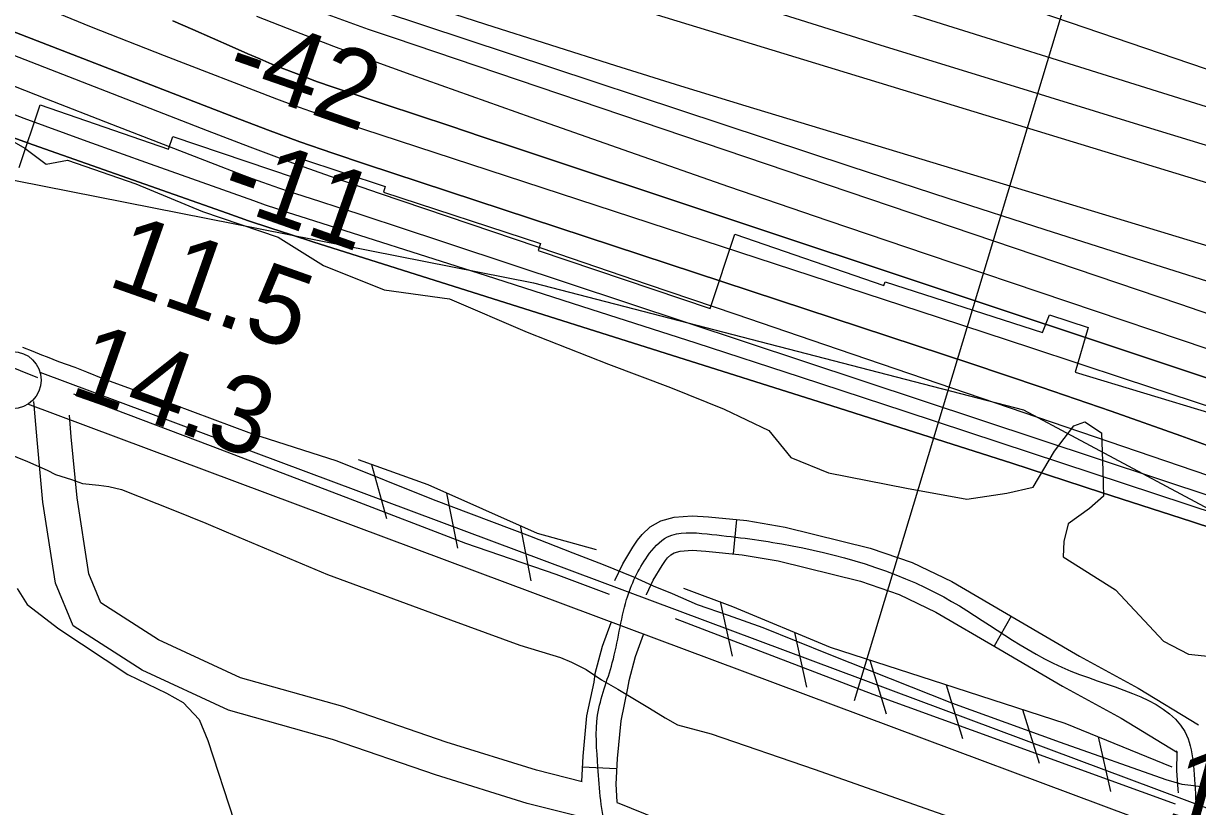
# Model space of a CAD drawing. Extents: x 3715084 to 3753216, y 488173 to 513963.
# Drawn here: x 3725388 to 3726412, y 498565 to 499247 of the extents above; entities that cross this region are included whole.
import ezdxf

# ---------------------------------------------------------------- set-up
doc = ezdxf.new("R2010")
doc.units = 0
for name, color, linetype in [('V-FLOD-BASE', 7, 'Continuous'), ('V-LEVE-TOET', 7, 'Continuous'), ('V-RIVR-EDGE', 7, 'Continuous'), ('V-RIVR-RANG', 7, 'Continuous'), ('V-ROAD-CNTR', 7, 'Continuous'), ('V-RRAP-FSHR', 7, 'Continuous'), ('V-RRAP-RVMT', 7, 'Continuous'), ('V-SITE-VEGE', 7, 'Continuous'), ('V-SURV-LINE', 7, 'Continuous'), ('V-TOPO-DPTH', 7, 'Continuous'), ('V-TOPO-MAJR', 7, 'Continuous'), ('V-TOPO-MINR', 7, 'Continuous'), ('V-TOPO-WATR', 7, 'Continuous')]:
    doc.layers.add(name, color=color, linetype=linetype)

msp = doc.modelspace()

# ---------------------------------------------------------------- linework, layer by layer
at = {"layer": 'V-FLOD-BASE'}
for points in [[(3723786.8, 499534.2), (3723869.2, 499496.9), (3723912.4, 499480.6), (3724034.1, 499437.4), (3724138.2, 499397.8), (3724259, 499355.5), (3724374, 499312.6), (3724499.4, 499266.7), (3724640.2, 499217.5), (3724785.1, 499164.3), (3724882.3, 499131.4), (3725004.5, 499087.7), (3725102.7, 499049.9), (3725207.1, 499013.5), (3725326.2, 498968.4), (3725400.8, 498938.7)], [(3725432.2, 498924.4), (3725551.2, 498879.3), (3725669.4, 498834.2), (3725773.9, 498794.2), (3725852.5, 498767.3), (3725898.9, 498749.7)], [(3725956.6, 498728.6), (3726128.8, 498662.7), (3726273.8, 498610.2), (3726392.3, 498567.1)]]:
    msp.add_lwpolyline(points, dxfattribs=at)
at = {"layer": 'V-LEVE-TOET'}
for points in [[(3725387.5, 498964.9), (3725396.6, 498961.5), (3725404.3, 498958.4), (3725409.1, 498956.5), (3725419.1, 498952.6), (3725433.2, 498947.5), (3725443.4, 498943.6), (3725457.7, 498937.8), (3725501.6, 498921.7), (3725587.2, 498889.7), (3725661.5, 498865.9), (3725745.6, 498832.3), (3725829.6, 498800.5), (3725867.4, 498785.9), (3725893.7, 498775.6), (3725920.1, 498764.8), (3725937.4, 498757), (3725953.9, 498750.4)], [(3725373.5, 498873), (3725392.1, 498865.3), (3725409, 498857.9), (3725416.3, 498854), (3725430.3, 498849.7), (3725439.9, 498846.3), (3725454.3, 498844.8), (3725462.9, 498843.6), (3725473.8, 498841.1), (3725520.2, 498822.6), (3725547.5, 498811.8), (3725565.2, 498804), (3725592.8, 498792.5), (3725653.6, 498766.8), (3725760.8, 498727.4), (3725821.2, 498705.5), (3725856.7, 498694.5), (3725866.2, 498690.6), (3725879, 498684.1), (3725892.2, 498675.3), (3725900.4, 498670.5), (3725906.4, 498667), (3725921, 498658.3), (3725934.2, 498650.4), (3725947.9, 498642.1), (3725958.4, 498636)], [(3725953.9, 498750.4), (3725975.8, 498740.8), (3726002.6, 498731.4), (3726033, 498720.9), (3726090.4, 498697.5), (3726197.3, 498655.1), (3726292.1, 498620.8), (3726384.3, 498588.2), (3726398.1, 498584.4), (3726406.1, 498583.3), (3726412.7, 498582.5), (3726416.3, 498581.6)], [(3725958.4, 498636), (3725987.9, 498628), (3726077.6, 498597.4), (3726210.5, 498550.6), (3726367.3, 498491.9), (3726599, 498410), (3726765.2, 498350.1), (3726863.8, 498316.9), (3726935.1, 498291.6), (3727054.7, 498243), (3727151.8, 498206.2), (3727209, 498188.4), (3727242.1, 498172.1), (3727277, 498151.6), (3727309.7, 498134.7), (3727402.2, 498100.1), (3727510.5, 498069), (3727562.5, 498053.8), (3727581.7, 498047.1), (3727583, 498046.7)]]:
    msp.add_lwpolyline(points, dxfattribs=at)
at = {"layer": 'V-RIVR-EDGE'}
msp.add_lwpolyline([(3725335.2, 499169.6), (3725389.7, 499138.3), (3725408.3, 499124.4), (3725426.9, 499128), (3725486.3, 499107.4), (3725544.5, 499083.2), (3725610.5, 499060.9), (3725650, 499036.2), (3725702.8, 499015), (3725759.8, 499007.1), (3725827.6, 498978.1), (3725898.4, 498950.3), (3725952.3, 498929.8), (3725999.1, 498911), (3726038.1, 498892.3), (3726057.2, 498868.9), (3726090.2, 498855.6), (3726158, 498842.2), (3726210.8, 498832.5), (3726245.7, 498837.8), (3726268.5, 498843.1), (3726287.2, 498874.3), (3726304, 498896.5), (3726313.7, 498900), (3726328, 498890.4), (3726329.2, 498857.4), (3726329.7, 498835.2), (3726317.7, 498824.4), (3726299, 498811.2), (3726295.4, 498795.6), (3726294.8, 498782.4), (3726340.3, 498753.5), (3726382.2, 498709), (3726403.8, 498697.5), (3726445.8, 498693.2)], dxfattribs=at)
at = {"layer": 'V-RIVR-RANG'}
msp.add_line((3726112.9, 498657.3), (3726390.3, 499576.4), dxfattribs=at)
at = {"layer": 'V-ROAD-CNTR'}
for p, q in [((3726009.9, 498814.8), (3726007, 498785)), ((3726249.5, 498730.5), (3726234.4, 498704.6)), ((3725905.5, 498597.6), (3725875.5, 498599))]:
    msp.add_line(p, q, dxfattribs=at)
for points in [[(3725877.4, 498554.9), (3725827.5, 498567.5), (3725747.7, 498592.5), (3725657.9, 498623.1), (3725567.2, 498648.8), (3725491.8, 498683.5), (3725431.7, 498722.3), (3725416.4, 498759.3), (3725405.5, 498830), (3725400.3, 498884.2), (3725397.5, 498917.7)], [(3725875.5, 498586.4), (3725835.7, 498596.4), (3725757, 498621), (3725666.9, 498651.8), (3725577.6, 498677), (3725506.3, 498709.9), (3725455.9, 498742.4), (3725445.5, 498767.4), (3725435.3, 498833.7), (3725430.1, 498886.9), (3725428.6, 498905.8)], [(3725904, 498761.6), (3725910.9, 498776.2), (3725919.7, 498790.9), (3725923.7, 498796.9), (3725927.7, 498801.9), (3725934.7, 498808.5), (3725943.9, 498813.6), (3725955.7, 498817), (3725971.2, 498818.1), (3725985.5, 498817.2), (3726018.9, 498813.9), (3726052.5, 498808.3), (3726126.5, 498790), (3726163, 498777.4), (3726197.7, 498760.7), (3726253.7, 498728.1), (3726308.8, 498695.8), (3726360.1, 498667.8), (3726412.7, 498635.9)], [(3725931.4, 498749.2), (3725931.4, 498749.4), (3725937.4, 498762.1), (3725945.1, 498774.9), (3725948, 498779.2), (3725949.8, 498781.5), (3725952.6, 498784.1), (3725955.5, 498785.7), (3725960.9, 498787.3), (3725971.4, 498788), (3725983.1, 498787.3), (3726014.9, 498784.2), (3726046.4, 498778.9), (3726118, 498761.2), (3726151.6, 498749.6), (3726183.6, 498734.1), (3726238.6, 498702.2), (3726294.1, 498669.7), (3726345.1, 498641.8), (3726394.3, 498612), (3726394, 498612.3), (3726393.3, 498613.4), (3726393.7, 498612.1), (3726393.6, 498596.3), (3726394.6, 498579.5), (3726394.8, 498576.8)], [(3725900.4, 498724.8), (3725892.8, 498704.1), (3725886.6, 498680.3), (3725885.6, 498673.2), (3725879.3, 498643.9), (3725876, 498608.6), (3725874.9, 498586.6)], [(3725928.6, 498714.5), (3725921.5, 498695.1), (3725916.1, 498674.4), (3725915.1, 498667.9), (3725909, 498639.4), (3725905.9, 498606.5), (3725904.9, 498584.3), (3725905.8, 498569), (3725906, 498567.8)], [(3725905.9, 498568.3), (3726015.8, 498523.8), (3726141.5, 498471.6), (3726283.2, 498412), (3726374.6, 498378.4), (3726355.2, 498260.8), (3726354.6, 498255.3), (3726352.2, 498234.1), (3726347.3, 498169.4), (3726344.4, 498110.1), (3726339.4, 498008.3), (3726336.3, 497977.2), (3726330.7, 497920.6), (3726327, 497845.4), (3726326.1, 497821), (3726325.6, 497787.2), (3726325.3, 497757.8)]]:
    msp.add_lwpolyline(points, dxfattribs=at)
msp.add_spline([(3725896.8, 497907), (3725901.6, 497928.8), (3725900.7, 497963.5), (3725897.7, 498015.4), (3725890.9, 498061.9), (3725848.5, 498171.1), (3725816.4, 498253), (3725801.2, 498306.9), (3725798.9, 498337.3), (3725811.7, 498376.3), (3725846.5, 498404.9), (3725886, 498425), (3725912.4, 498438.6), (3725916.4, 498460.8), (3725913.1, 498502), (3725897.5, 498542.1), (3725889.2, 498599.1), (3725888.9, 498644.4), (3725901.7, 498689.9), (3725914.2, 498745.1), (3725932.4, 498782.9), (3725949.7, 498799.7), (3725984.3, 498802.3), (3726049.5, 498793.6), (3726190.6, 498747.4), (3726301.5, 498682.8), (3726403.5, 498623.9), (3726408.6, 498596.7), (3726410.4, 498564)], degree=3, dxfattribs=at)
at = {"layer": 'V-RRAP-FSHR'}
for p, q in [((3725691.9, 498862.7), (3725704.8, 498815.6)), ((3725757.3, 498837.8), (3725766.7, 498789.9)), ((3725821.3, 498809.5), (3725830.7, 498761.5)), ((3725995.8, 498743.3), (3726006.3, 498695.7)), ((3726060.4, 498716.5), (3726071, 498668.8)), ((3726126.1, 498692.3), (3726140.3, 498645.6)), ((3726192.6, 498670.7), (3726207, 498624)), ((3726259.3, 498649.2), (3726273.7, 498602.6)), ((3726325.1, 498625.5), (3726335.8, 498577.9))]:
    msp.add_line(p, q, dxfattribs=at)
for points in [[(3719778.9, 501659.5), (3719780.9, 501658.9), (3720162.1, 501439.6), (3720517.2, 501248), (3721025.7, 501011.2), (3721396.9, 500844.8), (3721781.4, 500671.7), (3722343.7, 500424.7), (3722591.4, 500331.7), (3722936.5, 500157.7), (3723365.3, 499935.7), (3724002.2, 499670.3), (3724701.9, 499359), (3725287.2, 499128.8), (3725832.9, 499021), (3726260.1, 498910.4), (3726533.7, 498764.1), (3726929.4, 498511.1), (3727309.4, 498360.7), (3727495.4, 498332.2), (3727633.2, 498290.4), (3727809.2, 498206.8), (3728004.4, 498122.8), (3728249.6, 498078.8)], [(3725888, 498788.4), (3725836.6, 498802.7), (3725741.1, 498845.1), (3725680.5, 498866.8)], [(3726389.8, 498599), (3726296.5, 498637.2), (3726190.8, 498671.3), (3726092, 498703.4), (3726006.9, 498738.7), (3725964.1, 498754.6)]]:
    msp.add_lwpolyline(points, dxfattribs=at)
at = {"layer": 'V-RRAP-RVMT'}
for p, q in [((3725384.7, 499121.4), (3725402.9, 499176)), ((3725402.9, 499176), (3725514.8, 499137.6)), ((3725514.8, 499137.6), (3725518.6, 499148.5)), ((3725518.6, 499148.5), (3725624.4, 499112.9)), ((3725624.4, 499112.9), (3725629.9, 499129.5)), ((3725629.9, 499129.5), (3725703.6, 499105.1)), ((3725703.6, 499105.1), (3725702.3, 499100)), ((3725702.3, 499100), (3725839, 499055.2)), ((3725987, 498998.7), (3726008.5, 499063.6)), ((3726008.5, 499063.6), (3726138.3, 499018.6)), ((3725839, 499055.2), (3725837, 499049.3)), ((3725837, 499049.3), (3725987, 498998.7)), ((3726138.3, 499018.6), (3726139.5, 499021.9)), ((3726139.5, 499021.9), (3726276.8, 498977.9)), ((3726276.8, 498977.9), (3726282.9, 498993.1)), ((3726282.9, 498993.1), (3726316.4, 498982.1)), ((3726316.4, 498982.1), (3726305.1, 498943.3)), ((3726305.1, 498943.3), (3726424.2, 498907.3))]:
    msp.add_line(p, q, dxfattribs=at)
at = {"layer": 'V-SITE-VEGE'}
msp.add_lwpolyline([(3725382.9, 498754.6), (3725391.8, 498740.7), (3725419.2, 498719.6), (3725479.5, 498679.7), (3725513.2, 498663.6), (3725527.8, 498655.4), (3725541.6, 498640.7), (3725549.2, 498622.4), (3725572.2, 498552), (3725603.5, 498449.3), (3725632.9, 498373.6), (3725666.5, 498242.9), (3725713.2, 498091.3), (3725732.8, 498032.6), (3725733.4, 498026.3), (3725731.7, 498019.9), (3725725, 498014.9), (3725718.8, 498012.5), (3725708.8, 498013.2), (3725642.9, 498038.6), (3725538.5, 498071.8), (3725378.4, 498118.8)], dxfattribs=at)
at = {"layer": 'V-SURV-LINE'}
for points in [[(3725402.7, 498943.3), (3727093.5, 498312.2)], [(3727083, 498284.1), (3725392.3, 498915.2)]]:
    msp.add_lwpolyline(points, dxfattribs=at)
msp.add_circle((3725378.8, 498936.3), 25, dxfattribs=at)
at = {"layer": 'V-TOPO-DPTH'}
for points in [[(3725384.5, 499270.2), (3725447.6, 499244.1), (3725511.1, 499219), (3725609, 499181.5), (3725623.8, 499175.9), (3725638.8, 499170.5), (3725653.8, 499165.3), (3725668.9, 499160.2), (3726105.9, 499017.2), (3726186.5, 498990.8), (3726267.2, 498964.3), (3726347.8, 498937.8), (3726428.3, 498911.3)], [(3725384.5, 499270.2), (3725447.6, 499244.1), (3725511.1, 499219), (3725609, 499181.5), (3725623.8, 499175.9), (3725638.8, 499170.5), (3725653.8, 499165.3), (3725668.9, 499160.2), (3726105.9, 499017.2), (3726186.5, 498990.8), (3726267.2, 498964.3), (3726347.8, 498937.8), (3726428.3, 498911.3)], [(3726559.3, 498891.8), (3725816.5, 499139), (3725788.3, 499148.4), (3725760.1, 499157.8), (3725732, 499167.1), (3725703.8, 499176.5), (3725652.4, 499193.5), (3725649.9, 499194.3), (3725647.4, 499195.2), (3725644.9, 499196.1), (3725642.4, 499197), (3725626.1, 499203.3), (3725615.5, 499207.4), (3725605, 499211.7), (3725594.5, 499216.1), (3725584, 499220.6), (3725570.5, 499226.7), (3725553.2, 499234.2), (3725536, 499241.8), (3725518.7, 499249.2)], [(3726559.3, 498891.8), (3725816.5, 499139), (3725788.3, 499148.4), (3725760.1, 499157.8), (3725732, 499167.1), (3725703.8, 499176.5), (3725652.4, 499193.5), (3725649.9, 499194.3), (3725647.4, 499195.2), (3725644.9, 499196.1), (3725642.4, 499197), (3725626.1, 499203.3), (3725615.5, 499207.4), (3725605, 499211.7), (3725594.5, 499216.1), (3725584, 499220.6), (3725570.5, 499226.7), (3725553.2, 499234.2), (3725536, 499241.8), (3725518.7, 499249.2)], [(3727029, 498630), (3726986.2, 498648), (3726967.3, 498655.9), (3726915.1, 498677.9), (3726862.9, 498700), (3726810.8, 498722.1), (3726758.6, 498744.3), (3726649.9, 498790.6), (3726614.4, 498805.5), (3726578.8, 498819.9), (3726543, 498833.9), (3726507, 498847.4), (3726458, 498865.6), (3726397.3, 498887.7), (3726336.5, 498909.3), (3726275.4, 498930.2), (3726214.2, 498950.8), (3725686.5, 499124.4), (3725658, 499134), (3725629.5, 499144), (3725601.2, 499154.3), (3725573, 499165), (3725377.1, 499241)], [(3727029, 498630), (3726986.2, 498648), (3726967.3, 498655.9), (3726915.1, 498677.9), (3726862.9, 498700), (3726810.8, 498722.1), (3726758.6, 498744.3), (3726649.9, 498790.6), (3726614.4, 498805.5), (3726578.8, 498819.9), (3726543, 498833.9), (3726507, 498847.4), (3726458, 498865.6), (3726397.3, 498887.7), (3726336.5, 498909.3), (3726275.4, 498930.2), (3726214.2, 498950.8), (3725686.5, 499124.4), (3725658, 499134), (3725629.5, 499144), (3725601.2, 499154.3), (3725573, 499165), (3725377.1, 499241)], [(3725352.1, 499203.4), (3725408.6, 499181.3), (3725465.3, 499159.3), (3725560.5, 499122.3), (3725569.5, 499118.9), (3725578.6, 499115.5), (3725587.7, 499112.1), (3725596.8, 499108.9), (3725611.6, 499103.6), (3725613.3, 499103), (3725615, 499102.4), (3725616.7, 499101.8), (3725618.4, 499101.3), (3725646.6, 499092.2), (3725662.4, 499087.1), (3725678.2, 499082), (3725694, 499076.8), (3725709.8, 499071.6), (3726530.2, 498799.9)], [(3725352.1, 499203.4), (3725408.6, 499181.3), (3725465.3, 499159.3), (3725560.5, 499122.3), (3725569.5, 499118.9), (3725578.6, 499115.5), (3725587.7, 499112.1), (3725596.8, 499108.9), (3725611.6, 499103.6), (3725613.3, 499103), (3725615, 499102.4), (3725616.7, 499101.8), (3725618.4, 499101.3), (3725646.6, 499092.2), (3725662.4, 499087.1), (3725678.2, 499082), (3725694, 499076.8), (3725709.8, 499071.6), (3726530.2, 498799.9)], [(3726547.9, 498766.6), (3726406.4, 498813), (3726328.1, 498838.5), (3726249.8, 498863.9), (3726171.4, 498889), (3726093, 498913.9), (3725640.7, 499056.7), (3725622, 499062.8), (3725603.3, 499068.9), (3725584.7, 499075.2), (3725566.1, 499081.7), (3725397, 499141.4), (3725294.1, 499178.2)]]:
    msp.add_lwpolyline(points, dxfattribs=at)
at = {"layer": 'V-TOPO-MAJR'}
for points in [[(3726031.1, 499260.8), (3726139.6, 499227.1), (3726248.1, 499193.6), (3726356.7, 499160.3), (3726613.5, 499081.8), (3726631, 499076.3), (3726648.4, 499070.8), (3726665.8, 499065), (3726683.1, 499059.2), (3726783, 499024.8), (3726811.7, 499014.4), (3726840.2, 499003.5), (3726868.3, 498991.7), (3726896.2, 498979.3), (3726923.8, 498966.3), (3726951.4, 498953.1), (3726978.8, 498939.7), (3727006.1, 498926), (3727045.3, 498906.2)], [(3725591.6, 499253.3), (3725625.1, 499240.2), (3725658.6, 499227.3), (3725692.4, 499214.8), (3725726.2, 499202.6), (3725830.6, 499165.5), (3725916.8, 499135.2), (3726003.1, 499105.1), (3726089.5, 499075.4), (3726176, 499046), (3726543.2, 498922.4), (3726572.4, 498912.3), (3726601.5, 498901.9), (3726630.5, 498890.9), (3726659.3, 498879.7), (3726798.5, 498824.1), (3726826.1, 498812.5), (3726853.4, 498800.2), (3726880.3, 498787.1), (3726906.9, 498773.3), (3726933.4, 498759.2), (3726960, 498745.4), (3726986.9, 498732.1), (3727013.8, 498718.9)]]:
    msp.add_lwpolyline(points, dxfattribs=at)
at = {"layer": 'V-TOPO-MINR'}
for points in [[(3725245.4, 499590.8), (3725645.7, 499429.6), (3725682.4, 499415.1), (3725719.3, 499400.9), (3725756.3, 499387.2), (3725793.5, 499373.9), (3725830.8, 499360.9), (3725868.2, 499348.3), (3725905.8, 499336), (3725943.4, 499324), (3726592.7, 499120.3), (3726624.6, 499110.2), (3726656.5, 499099.8), (3726688.2, 499089.3), (3726719.9, 499078.5), (3726916.9, 499010.9), (3726962.6, 498994.2), (3727007.9, 498976.3)], [(3725373.4, 499579.9), (3725463.2, 499544.7), (3725553.2, 499510.1), (3725691.8, 499457.2), (3725712.7, 499449.4), (3725733.5, 499441.7), (3725754.5, 499434.3), (3725775.5, 499427), (3726484.2, 499185.3), (3726514.1, 499175.3), (3726544, 499165.4), (3726574, 499155.7), (3726604, 499146.2), (3726634, 499136.6), (3726664, 499127), (3726693.9, 499117.1), (3726723.8, 499107.1), (3727059.7, 498993.4)], [(3725378.1, 499360), (3725474.1, 499323.1), (3725622, 499266.6), (3725644.2, 499258.2), (3725666.6, 499250.1), (3725689, 499242.1), (3725711.5, 499234.4), (3726396.1, 499002.7), (3726431.6, 498990.6), (3726467.2, 498978.5), (3726502.7, 498966.3), (3726538.2, 498954), (3726573.6, 498941.4), (3726608.8, 498928.3), (3726643.8, 498914.7), (3726678.6, 498900.6), (3726880.6, 498816.8), (3726916.9, 498801.1), (3726952.8, 498784.5), (3726988, 498766.8), (3727022.9, 498748.3)], [(3725754.2, 499311.9), (3726524.1, 499076.6), (3726543.5, 499070.7), (3726562.8, 499064.9), (3726582.2, 499059), (3726601.6, 499053.2), (3726634.5, 499043.4), (3726637.4, 499042.5), (3726640.3, 499041.6), (3726643.2, 499040.7), (3726646.1, 499039.7), (3726661.2, 499034.5), (3726666.8, 499032.5), (3726672.3, 499030.4), (3726677.8, 499028.2), (3726683.2, 499026), (3726688.6, 499023.6), (3726694, 499021.2), (3726699.4, 499018.7), (3726704.7, 499016.3), (3726889.2, 498930), (3726941.6, 498905.5), (3726994, 498881.1), (3727046.4, 498856.8)], [(3725159.5, 499305.5), (3725548.5, 499153.8), (3725585.8, 499139.6), (3725623.1, 499125.7), (3725660.7, 499112.3), (3725698.4, 499099.3), (3725777.5, 499072.5), (3725854.8, 499046.3), (3725932.1, 499020), (3726009.4, 498993.7), (3726086.7, 498967.4), (3726520.2, 498819.5)], [(3725689.6, 499279.4), (3725791.2, 499246.4), (3725847.7, 499228.3), (3725904.4, 499210.3), (3725961.1, 499192.7), (3726018, 499175.3), (3726575, 499006.6), (3726600.6, 498998.5), (3726626, 498990.1), (3726651.2, 498981), (3726676.2, 498971.5), (3726778.7, 498931.4), (3726815.3, 498916.8), (3726851.8, 498901.8), (3726888.1, 498886.4), (3726924.2, 498870.6), (3726960.2, 498854.4), (3726996.1, 498838.1), (3727031.8, 498821.4)], [(3725384.5, 499270.2), (3725447.6, 499244.1), (3725511.1, 499219), (3725609, 499181.5), (3725623.8, 499175.9), (3725638.8, 499170.5), (3725653.8, 499165.3), (3725668.9, 499160.2), (3726105.9, 499017.2), (3726186.5, 498990.8), (3726267.2, 498964.3), (3726347.8, 498937.8), (3726428.3, 498911.3)], [(3725700.3, 499257.7), (3726109.6, 499122.5), (3726194.1, 499094.9), (3726278.7, 499067.5), (3726363.4, 499040.5), (3726448.2, 499013.7), (3726596.8, 498967.3), (3726607.3, 498963.9), (3726617.8, 498960.3), (3726628.1, 498956.6), (3726638.5, 498952.6), (3726678.1, 498937.1), (3726694.5, 498930.6), (3726710.8, 498924), (3726727, 498917.2), (3726743.3, 498910.4), (3726759.4, 498903.4), (3726775.6, 498896.4), (3726791.7, 498889.3), (3726807.8, 498882.2), (3726976.1, 498807.7), (3727018.3, 498788.2)], [(3725518.7, 499249.2), (3725536, 499241.8), (3725553.2, 499234.2), (3725570.5, 499226.7), (3725584, 499220.6), (3725594.5, 499216.1), (3725605, 499211.7), (3725615.5, 499207.4), (3725626.1, 499203.3), (3725642.4, 499197), (3725644.9, 499196.1), (3725647.4, 499195.2), (3725649.9, 499194.3), (3725652.4, 499193.5), (3725703.8, 499176.5), (3725732, 499167.1), (3725760.1, 499157.8), (3725788.3, 499148.4), (3725816.5, 499139), (3726559.3, 498891.8)], [(3725377.1, 499241), (3725573, 499165), (3725601.2, 499154.3), (3725629.5, 499144), (3725658, 499134), (3725686.5, 499124.4), (3726214.2, 498950.8), (3726275.4, 498930.2), (3726336.5, 498909.3), (3726397.3, 498887.7), (3726458, 498865.6), (3726507, 498847.4), (3726543, 498833.9), (3726578.8, 498819.9), (3726614.4, 498805.5), (3726649.9, 498790.6), (3726758.6, 498744.3), (3726810.8, 498722.1), (3726862.9, 498700), (3726915.1, 498677.9), (3726967.3, 498655.9), (3726986.2, 498648), (3727029, 498630)], [(3725352.1, 499203.4), (3725408.6, 499181.3), (3725465.3, 499159.3), (3725560.5, 499122.3), (3725569.5, 499118.9), (3725578.6, 499115.5), (3725587.7, 499112.1), (3725596.8, 499108.9), (3725611.6, 499103.6), (3725613.3, 499103), (3725615, 499102.4), (3725616.7, 499101.8), (3725618.4, 499101.3), (3725646.6, 499092.2), (3725662.4, 499087.1), (3725678.2, 499082), (3725694, 499076.8), (3725709.8, 499071.6), (3726530.2, 498799.9)], [(3725334.1, 499185.3), (3725388.8, 499164.6), (3725443.8, 499144.5), (3725498.8, 499124.7), (3725588.9, 499092.7), (3725599, 499089.1), (3725609.1, 499085.7), (3725619.3, 499082.3), (3725629.5, 499079), (3725791.8, 499027.4), (3725883.1, 498998.1), (3725974.4, 498968.8), (3726065.5, 498939.1), (3726156.6, 498909.2), (3726539, 498783.3)]]:
    msp.add_lwpolyline(points, dxfattribs=at)
at = {"layer": 'V-TOPO-WATR'}
msp.add_lwpolyline([(3725294.1, 499178.2), (3725397, 499141.4), (3725566.1, 499081.7), (3725584.7, 499075.2), (3725603.3, 499068.9), (3725622, 499062.8), (3725640.7, 499056.7), (3726093, 498913.9), (3726171.4, 498889), (3726249.8, 498863.9), (3726328.1, 498838.5), (3726406.4, 498813), (3726547.9, 498766.6)], dxfattribs=at)

# ---------------------------------------------------------------- texts
at = {"layer": 'V-RIVR-RANG'}
for s, rotation, p in [('-42', 340.8837, (3725561.7, 499195)), ('-11', 340.5983, (3725557.3, 499091)), ('11.5', 340.5983, (3725460.1, 499019.2)), ('14.3', 340.5983, (3725427.1, 498924.8)), ('11.7', 344.3683, (3726381.9, 498553.7))]:
    msp.add_text(s, height=67, rotation=rotation, dxfattribs=at).set_placement(p)

doc.saveas('drawing.dxf')
